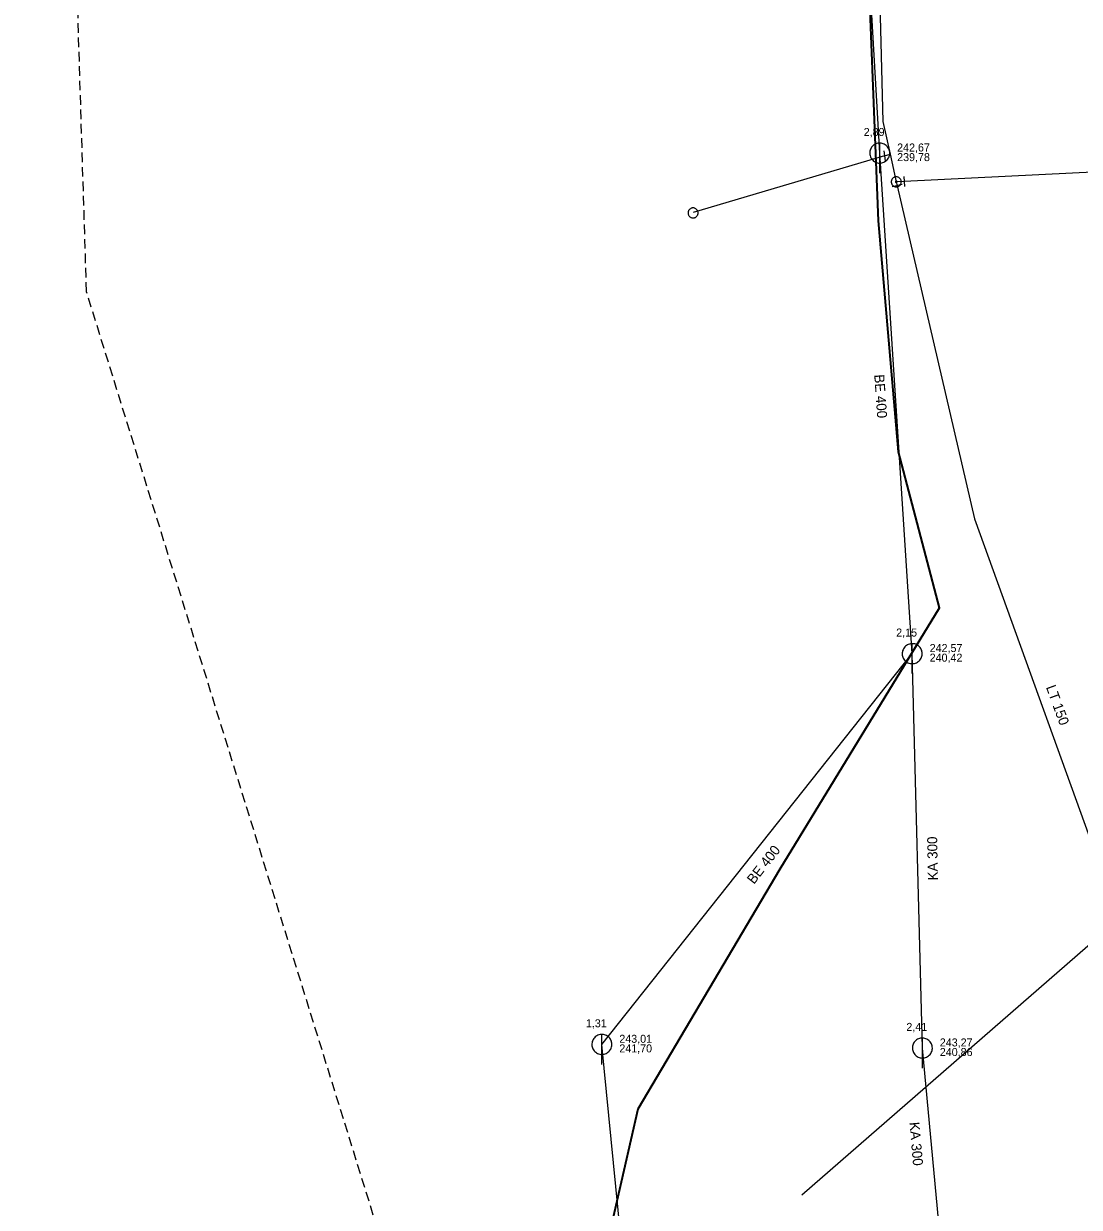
# Model space of a CAD drawing. Extents: x -777996 to -777727, y -976581 to -976199.
# Drawn here: x -777995.4 to -777889.9, y -976496.9 to -976378.6 of the extents above; entities that cross this region are included whole.
import ezdxf

# ---------------------------------------------------------------- set-up
doc = ezdxf.new("R2010")
doc.units = 0
doc.header["$LTSCALE"] = 0.32
doc.linetypes.add('MEDIUM_DASHED', pattern=[4.5, 3, -1.5])
for name, color, linetype, lineweight in [('1', 7, 'MEDIUM_DASHED', 25), ('13', 7, 'Continuous', 13), ('14', 7, 'Continuous', 25), ('17', 7, 'Continuous', 25), ('22', 7, 'Continuous', 13), ('23', 7, 'Continuous', 13), ('34', 7, 'Continuous', 13), ('47', 7, 'Continuous', 13)]:
    doc.layers.add(name, color=color, linetype=linetype, lineweight=lineweight)

msp = doc.modelspace()

# ---------------------------------------------------------------- linework, layer by layer
at = {"layer": '1'}
msp.add_lwpolyline([(-777995.417, -976203.033), (-777848.18, -976198.846), (-777864.927, -976230.247), (-777726.762, -976491.225), (-777789.565, -976581.242), (-777941.686, -976558.215), (-777989.136, -976405.396)], close=True, dxfattribs=at)
at = {"layer": '13'}
for p, q in [((-777909.39, -976391.8), (-777928.5, -976397.482)), ((-777885.941, -976468.086), (-777917.634, -976495.726))]:
    msp.add_line(p, q, dxfattribs=at)
at = {"layer": '14'}
for p, q in [((-777909.866, -976391.528), (-777912.781, -976340.699)), ((-777906.618, -976441.576), (-777909.866, -976391.528)), ((-777937.634, -976480.646), (-777906.618, -976441.576)), ((-777905.603, -976481.009), (-777906.618, -976441.576)), ((-777933.671, -976521.223), (-777937.634, -976480.646)), ((-777903.695, -976501.491), (-777905.603, -976481.009))]:
    msp.add_line(p, q, dxfattribs=at)
at = {"layer": '14', "lineweight": 13}
for p, q in [((-777909.39, -976391.8), (-777908.826, -976391.645)), ((-777907.426, -976394.361), (-777908.211, -976394.397)), ((-777908.211, -976394.397), (-777908.12, -976394.786))]:
    msp.add_line(p, q, dxfattribs=at)
at = {"layer": '17', "lineweight": 35}
msp.add_lwpolyline([(-777904.212, -976563.887), (-777912, -976559.699), (-777928.6, -976551.899), (-777943.399, -976543.899), (-777945.899, -976539.199), (-777934, -976487.1), (-777919.8, -976463.1), (-777903.899, -976437), (-777908, -976421.399), (-777910, -976398.3), (-777913.399, -976312.399), (-777914.899, -976265.1)], dxfattribs=at)
at = {"layer": '17'}
for points in [[(-777913.344, -976268.857), (-777912.789, -976277.989), (-777911.427, -976308.781), (-777911.171, -976324.191), (-777910.419, -976354.125), (-777909.559, -976388.363), (-777908.825, -976391.646), (-777908.211, -976394.397)], [(-777835.751, -976390.694), (-777871.295, -976392.649), (-777871.809, -976392.66), (-777874.445, -976392.723), (-777907.426, -976394.361)], [(-777908.12, -976394.786), (-777900.403, -976428.079), (-777886.159, -976467.482), (-777885.941, -976468.086)]]:
    msp.add_lwpolyline(points, dxfattribs=at)
at = {"layer": '22'}
for p, q in [((-777909.866, -976393.528), (-777909.865, -976390.528)), ((-777906.618, -976443.576), (-777906.617, -976440.576)), ((-777937.634, -976482.646), (-777937.633, -976479.646)), ((-777905.604, -976483.009), (-777905.603, -976480.009))]:
    msp.add_line(p, q, dxfattribs=at)
for points in [[(-777908.866, -976391.528), (-777908.871, -976391.419), (-777908.889, -976391.311), (-777908.919, -976391.205), (-777908.959, -976391.104), (-777909.011, -976391.007), (-777909.073, -976390.917), (-777909.145, -976390.834), (-777909.225, -976390.76), (-777909.313, -976390.694), (-777909.407, -976390.639), (-777909.507, -976390.594), (-777909.612, -976390.561), (-777909.719, -976390.539), (-777909.828, -976390.529), (-777909.938, -976390.531), (-777910.046, -976390.545), (-777910.153, -976390.57), (-777910.256, -976390.607), (-777910.354, -976390.656), (-777910.446, -976390.714), (-777910.532, -976390.783), (-777910.609, -976390.86), (-777910.678, -976390.946), (-777910.737, -976391.038), (-777910.785, -976391.136), (-777910.822, -976391.239), (-777910.848, -976391.346), (-777910.862, -976391.454), (-777910.865, -976391.564), (-777910.855, -976391.673), (-777910.834, -976391.78), (-777910.8, -976391.884), (-777910.756, -976391.984), (-777910.701, -976392.079), (-777910.635, -976392.167), (-777910.561, -976392.247), (-777910.478, -976392.319), (-777910.388, -976392.381), (-777910.292, -976392.433), (-777910.19, -976392.474), (-777910.085, -976392.504), (-777909.977, -976392.522), (-777909.867, -976392.528), (-777909.758, -976392.522), (-777909.65, -976392.504), (-777909.545, -976392.475), (-777909.443, -976392.434), (-777909.346, -976392.382), (-777909.256, -976392.32), (-777909.173, -976392.249), (-777909.098, -976392.169), (-777909.033, -976392.081), (-777908.977, -976391.987), (-777908.933, -976391.887), (-777908.899, -976391.783), (-777908.877, -976391.675), (-777908.867, -976391.566)], [(-777905.618, -976441.576), (-777905.623, -976441.467), (-777905.641, -976441.359), (-777905.671, -976441.253), (-777905.711, -976441.152), (-777905.763, -976441.055), (-777905.825, -976440.965), (-777905.897, -976440.882), (-777905.977, -976440.808), (-777906.065, -976440.742), (-777906.159, -976440.687), (-777906.259, -976440.642), (-777906.364, -976440.609), (-777906.471, -976440.587), (-777906.58, -976440.577), (-777906.69, -976440.579), (-777906.798, -976440.593), (-777906.905, -976440.618), (-777907.008, -976440.655), (-777907.106, -976440.704), (-777907.198, -976440.762), (-777907.284, -976440.831), (-777907.361, -976440.908), (-777907.43, -976440.994), (-777907.489, -976441.086), (-777907.537, -976441.184), (-777907.574, -976441.287), (-777907.6, -976441.394), (-777907.614, -976441.502), (-777907.617, -976441.612), (-777907.607, -976441.721), (-777907.586, -976441.828), (-777907.552, -976441.932), (-777907.508, -976442.032), (-777907.453, -976442.127), (-777907.387, -976442.215), (-777907.313, -976442.295), (-777907.23, -976442.367), (-777907.14, -976442.429), (-777907.044, -976442.481), (-777906.942, -976442.522), (-777906.837, -976442.552), (-777906.729, -976442.57), (-777906.619, -976442.576), (-777906.51, -976442.57), (-777906.402, -976442.552), (-777906.297, -976442.523), (-777906.195, -976442.482), (-777906.098, -976442.43), (-777906.008, -976442.368), (-777905.925, -976442.297), (-777905.85, -976442.217), (-777905.785, -976442.129), (-777905.729, -976442.035), (-777905.685, -976441.935), (-777905.651, -976441.831), (-777905.629, -976441.723), (-777905.619, -976441.614)], [(-777936.634, -976480.646), (-777936.639, -976480.537), (-777936.657, -976480.429), (-777936.687, -976480.323), (-777936.727, -976480.222), (-777936.779, -976480.125), (-777936.841, -976480.035), (-777936.913, -976479.952), (-777936.993, -976479.878), (-777937.081, -976479.812), (-777937.175, -976479.757), (-777937.275, -976479.712), (-777937.38, -976479.679), (-777937.487, -976479.657), (-777937.596, -976479.647), (-777937.706, -976479.649), (-777937.814, -976479.663), (-777937.921, -976479.688), (-777938.024, -976479.725), (-777938.122, -976479.774), (-777938.214, -976479.832), (-777938.3, -976479.901), (-777938.377, -976479.978), (-777938.446, -976480.064), (-777938.505, -976480.156), (-777938.553, -976480.254), (-777938.59, -976480.357), (-777938.616, -976480.464), (-777938.63, -976480.572), (-777938.633, -976480.682), (-777938.623, -976480.791), (-777938.602, -976480.898), (-777938.568, -976481.002), (-777938.524, -976481.102), (-777938.469, -976481.197), (-777938.403, -976481.285), (-777938.329, -976481.365), (-777938.246, -976481.437), (-777938.156, -976481.499), (-777938.06, -976481.551), (-777937.958, -976481.592), (-777937.853, -976481.622), (-777937.745, -976481.64), (-777937.635, -976481.646), (-777937.526, -976481.64), (-777937.418, -976481.622), (-777937.313, -976481.593), (-777937.211, -976481.552), (-777937.114, -976481.5), (-777937.024, -976481.438), (-777936.941, -976481.367), (-777936.866, -976481.287), (-777936.801, -976481.199), (-777936.745, -976481.105), (-777936.701, -976481.005), (-777936.667, -976480.901), (-777936.645, -976480.793), (-777936.635, -976480.684)], [(-777904.604, -976481.009), (-777904.609, -976480.9), (-777904.627, -976480.792), (-777904.657, -976480.686), (-777904.697, -976480.585), (-777904.749, -976480.488), (-777904.811, -976480.398), (-777904.883, -976480.315), (-777904.963, -976480.241), (-777905.051, -976480.175), (-777905.145, -976480.12), (-777905.245, -976480.075), (-777905.35, -976480.042), (-777905.457, -976480.02), (-777905.566, -976480.01), (-777905.676, -976480.012), (-777905.784, -976480.026), (-777905.891, -976480.051), (-777905.994, -976480.088), (-777906.092, -976480.137), (-777906.184, -976480.195), (-777906.27, -976480.264), (-777906.347, -976480.341), (-777906.416, -976480.427), (-777906.475, -976480.519), (-777906.523, -976480.617), (-777906.56, -976480.72), (-777906.586, -976480.827), (-777906.6, -976480.935), (-777906.603, -976481.045), (-777906.593, -976481.154), (-777906.572, -976481.261), (-777906.538, -976481.365), (-777906.494, -976481.465), (-777906.439, -976481.56), (-777906.373, -976481.648), (-777906.299, -976481.728), (-777906.216, -976481.8), (-777906.126, -976481.862), (-777906.03, -976481.914), (-777905.928, -976481.955), (-777905.823, -976481.985), (-777905.715, -976482.003), (-777905.605, -976482.009), (-777905.496, -976482.003), (-777905.388, -976481.985), (-777905.283, -976481.956), (-777905.181, -976481.915), (-777905.084, -976481.863), (-777904.994, -976481.801), (-777904.911, -976481.73), (-777904.836, -976481.65), (-777904.771, -976481.562), (-777904.715, -976481.468), (-777904.671, -976481.368), (-777904.637, -976481.264), (-777904.615, -976481.156), (-777904.605, -976481.047)]]:
    msp.add_lwpolyline(points, close=True, dxfattribs=at)
at = {"layer": '23'}
for points in [[(-777928.025, -976397.428), (-777928.036, -976397.376), (-777928.053, -976397.326), (-777928.075, -976397.279), (-777928.101, -976397.234), (-777928.132, -976397.192), (-777928.168, -976397.153), (-777928.206, -976397.118), (-777928.248, -976397.088), (-777928.294, -976397.062), (-777928.341, -976397.041), (-777928.392, -976397.024), (-777928.444, -976397.013), (-777928.495, -976397.008), (-777928.547, -976397.009), (-777928.598, -976397.014), (-777928.651, -976397.026), (-777928.699, -976397.041), (-777928.749, -976397.063), (-777928.792, -976397.088), (-777928.835, -976397.119), (-777928.874, -976397.156), (-777928.909, -976397.195), (-777928.94, -976397.238), (-777928.966, -976397.282), (-777928.987, -976397.33), (-777929.002, -976397.381), (-777929.013, -976397.431), (-777929.018, -976397.483), (-777929.017, -976397.536), (-777929.012, -976397.588), (-777929.002, -976397.639), (-777928.985, -976397.689), (-777928.964, -976397.737), (-777928.938, -976397.782), (-777928.906, -976397.822), (-777928.871, -976397.862), (-777928.832, -976397.897), (-777928.789, -976397.928), (-777928.744, -976397.954)], [(-777928.749, -976397.063), (-777928.792, -976397.088), (-777928.835, -976397.119), (-777928.874, -976397.156), (-777928.909, -976397.195), (-777928.94, -976397.238), (-777928.966, -976397.282), (-777928.987, -976397.33), (-777929.002, -976397.381), (-777929.013, -976397.431), (-777929.018, -976397.483), (-777929.017, -976397.536), (-777929.012, -976397.588), (-777929.002, -976397.639), (-777928.985, -976397.689), (-777928.964, -976397.737), (-777928.938, -976397.782), (-777928.906, -976397.822), (-777928.871, -976397.862), (-777928.832, -976397.897), (-777928.789, -976397.928), (-777928.744, -976397.954), (-777928.697, -976397.975), (-777928.646, -976397.991), (-777928.596, -976398.002), (-777928.543, -976398.006), (-777928.491, -976398.006), (-777928.439, -976398.001), (-777928.389, -976397.989), (-777928.338, -976397.973), (-777928.29, -976397.952), (-777928.246, -976397.925), (-777928.203, -976397.894), (-777928.164, -976397.86), (-777928.13, -976397.82), (-777928.099, -976397.779), (-777928.073, -976397.733), (-777928.051, -976397.684), (-777928.035, -976397.635), (-777928.025, -976397.583)], [(-777928.744, -976397.954), (-777928.697, -976397.975), (-777928.646, -976397.991), (-777928.596, -976398.002), (-777928.543, -976398.006), (-777928.491, -976398.006), (-777928.439, -976398.001), (-777928.389, -976397.989), (-777928.338, -976397.973), (-777928.29, -976397.952), (-777928.246, -976397.925), (-777928.203, -976397.894), (-777928.164, -976397.86), (-777928.13, -976397.82), (-777928.099, -976397.779), (-777928.073, -976397.733), (-777928.051, -976397.684), (-777928.035, -976397.635), (-777928.025, -976397.583), (-777928.021, -976397.531), (-777928.02, -976397.48), (-777928.025, -976397.428), (-777928.036, -976397.376), (-777928.053, -976397.326), (-777928.075, -976397.279), (-777928.101, -976397.234), (-777928.132, -976397.192), (-777928.168, -976397.153), (-777928.206, -976397.118), (-777928.248, -976397.088), (-777928.294, -976397.062), (-777928.341, -976397.041), (-777928.392, -976397.024), (-777928.444, -976397.013), (-777928.495, -976397.008), (-777928.547, -976397.009), (-777928.598, -976397.014), (-777928.651, -976397.026), (-777928.699, -976397.041), (-777928.749, -976397.063)], [(-777928.025, -976397.583), (-777928.021, -976397.531), (-777928.02, -976397.48), (-777928.025, -976397.428)]]:
    msp.add_lwpolyline(points, dxfattribs=at)
at = {"layer": '34'}
for p, q in [((-777909.465, -976391.305), (-777909.315, -976392.294)), ((-777907.449, -976393.861), (-777907.403, -976394.86)), ((-777907.633, -976394.672), (-777908.607, -976394.898))]:
    msp.add_line(p, q, dxfattribs=at)
at = {"layer": '47'}
for points in [[(-777908.102, -976394.884), (-777908.051, -976394.87), (-777908.002, -976394.851), (-777907.957, -976394.827), (-777907.913, -976394.798), (-777907.872, -976394.765), (-777907.836, -976394.727), (-777907.804, -976394.686), (-777907.776, -976394.642), (-777907.752, -976394.595), (-777907.733, -976394.546), (-777907.72, -976394.495), (-777907.713, -976394.443), (-777907.711, -976394.391), (-777907.714, -976394.339), (-777907.723, -976394.288), (-777907.737, -976394.237), (-777907.756, -976394.188), (-777907.781, -976394.142), (-777907.809, -976394.099), (-777907.842, -976394.058), (-777907.88, -976394.022), (-777907.921, -976393.989), (-777907.966, -976393.961), (-777908.012, -976393.937), (-777908.061, -976393.919), (-777908.112, -976393.906), (-777908.164, -976393.898), (-777908.216, -976393.897), (-777908.268, -976393.9), (-777908.319, -976393.909), (-777908.37, -976393.923), (-777908.419, -976393.942), (-777908.465, -976393.966), (-777908.508, -976393.995), (-777908.549, -976394.028), (-777908.586, -976394.065), (-777908.618, -976394.106), (-777908.647, -976394.151), (-777908.67, -976394.198), (-777908.688, -976394.247), (-777908.701, -976394.298), (-777908.709, -976394.349), (-777908.71, -976394.402), (-777908.707, -976394.454), (-777908.698, -976394.505), (-777908.684, -976394.556), (-777908.665, -976394.605), (-777908.642, -976394.65), (-777908.612, -976394.694), (-777908.579, -976394.735), (-777908.542, -976394.772), (-777908.501, -976394.804), (-777908.457, -976394.832), (-777908.409, -976394.855), (-777908.36, -976394.874), (-777908.309, -976394.887), (-777908.258, -976394.894), (-777908.205, -976394.896), (-777908.153, -976394.893)], [(-777908.193, -976394.477), (-777908.184, -976394.475), (-777908.176, -976394.471), (-777908.169, -976394.467), (-777908.162, -976394.463), (-777908.155, -976394.457), (-777908.149, -976394.45), (-777908.144, -976394.444), (-777908.139, -976394.437), (-777908.136, -976394.429), (-777908.132, -976394.421), (-777908.13, -976394.412), (-777908.129, -976394.404), (-777908.129, -976394.396), (-777908.129, -976394.387), (-777908.13, -976394.379), (-777908.132, -976394.37), (-777908.136, -976394.362), (-777908.14, -976394.355), (-777908.144, -976394.348), (-777908.15, -976394.341), (-777908.157, -976394.335), (-777908.163, -976394.33), (-777908.17, -976394.325), (-777908.178, -976394.321), (-777908.186, -976394.318), (-777908.195, -976394.316), (-777908.203, -976394.315), (-777908.211, -976394.315), (-777908.22, -976394.315), (-777908.228, -976394.316), (-777908.237, -976394.318), (-777908.245, -976394.322), (-777908.252, -976394.326), (-777908.259, -976394.33), (-777908.266, -976394.336), (-777908.272, -976394.342), (-777908.277, -976394.349), (-777908.282, -976394.356), (-777908.286, -976394.364), (-777908.289, -976394.372), (-777908.291, -976394.381), (-777908.292, -976394.389), (-777908.292, -976394.397), (-777908.292, -976394.406), (-777908.291, -976394.414), (-777908.289, -976394.423), (-777908.285, -976394.431), (-777908.281, -976394.438), (-777908.277, -976394.445), (-777908.271, -976394.452), (-777908.265, -976394.458), (-777908.258, -976394.463), (-777908.251, -976394.468), (-777908.243, -976394.471), (-777908.235, -976394.475), (-777908.226, -976394.477), (-777908.218, -976394.478), (-777908.21, -976394.478), (-777908.201, -976394.478)]]:
    msp.add_lwpolyline(points, close=True, dxfattribs=at)

# ---------------------------------------------------------------- texts
at = {"layer": '1'}
for s, p in [('2,89', (-777911.466, -976389.816)), ('2,15', (-777908.218, -976439.864)), ('1,31', (-777939.233, -976478.934)), ('2,41', (-777907.204, -976479.297))]:
    msp.add_text(s, height=0.8, dxfattribs=at).set_placement(p)
for s, rotation, p in [('BE 400', 274, (-777910.417, -976413.686)), ('LT 150', 290, (-777893.265, -976444.925)), ('KA 300', 91, (-777904.049, -976464.24)), ('BE 400', 52, (-777922.435, -976464.694)), ('KA 300', 275, (-777906.904, -976488.446))]:
    msp.add_text(s, height=1, rotation=rotation, dxfattribs=at).set_placement(p)
at = {"layer": '22'}
for s, p in [('242,67', (-777908.123, -976391.367)), ('239,78', (-777908.123, -976392.327)), ('242,57', (-777904.875, -976441.415)), ('240,42', (-777904.875, -976442.375)), ('243,01', (-777935.891, -976480.485)), ('241,70', (-777935.891, -976481.445)), ('243,27', (-777903.861, -976480.848)), ('240,86', (-777903.861, -976481.808))]:
    msp.add_text(s, height=0.8, dxfattribs=at).set_placement(p)

doc.saveas('drawing.dxf')
